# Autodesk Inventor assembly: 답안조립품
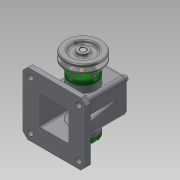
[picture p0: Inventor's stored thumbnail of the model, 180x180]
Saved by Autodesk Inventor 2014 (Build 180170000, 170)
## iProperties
Created: 2016-02
Part Number: 답안조립품
Document SubType Name: Assembly
Designer: user
Author: user
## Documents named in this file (15)
- C:\Users\user\Desktop\460212V1003\답안조립품.iam
- C:\Users\user\Desktop\460212V1003\본체.ipt
- C:\Users\user\Desktop\460212V1003\뒤커버.ipt
- C:\Users\user\Desktop\460212V1003\앞커버.ipt
- C:\Users\user\Desktop\460212V1003\편심축.ipt
- C:\Users\user\Desktop\460212V1003\베어링 12 x 32 x 10.ipt
- C:\Users\user\Desktop\460212V1003\링크.ipt
- C:\Users\user\Desktop\460212V1003\오일실 12 25 7.ipt
- C:\Users\user\Desktop\460212V1003\볼트 M4 x 12.ipt
- C:\Users\user\Desktop\460212V1003\키 4 x 4 x 10.ipt
- C:\Users\user\Desktop\460212V1003\V벨트풀리.ipt
- C:\Users\user\Desktop\460212V1003\멈춤나사 M3x8.ipt
- C:\Users\user\Desktop\460212V1003\슬라이드.ipt
- C:\Users\user\Desktop\460212V1003\핀 5 x 18.ipt
- C:\Users\user\Desktop\460212V1003\부시.ipt
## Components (10 placed, 3 different names)
1. ISO 4762 M4 x 12:1 — Insert:8
2. ISO 4762 M4 x 12:2 — Insert:9
3. ISO 4762 M4 x 12:3 — Insert:10
4. ISO 4762 M4 x 12:4 — Insert:11
5. ISO 4762 M4 x 12:5 — Insert:12
6. ISO 4762 M4 x 12:6 — Insert:13
7. ISO 4762 M4 x 12:7 — Insert:14
8. ISO 4762 M4 x 12:8 — Insert:15
9. V벨트풀리:1 — Mate:3, Insert:18
10. 핀 5 x 18:1 — Insert:19
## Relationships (11: Insert 10, Mate 1)
- Insert:8: ISO 4762 M4 x 12:1
- Insert:9: ISO 4762 M4 x 12:2
- Insert:10: ISO 4762 M4 x 12:3
- Insert:11: ISO 4762 M4 x 12:4
- Insert:12: ISO 4762 M4 x 12:5
- Insert:13: ISO 4762 M4 x 12:6
- Insert:14: ISO 4762 M4 x 12:7
- Insert:15: ISO 4762 M4 x 12:8
- Mate:3: V벨트풀리:1
- Insert:18: V벨트풀리:1
- Insert:19: 핀 5 x 18:1
